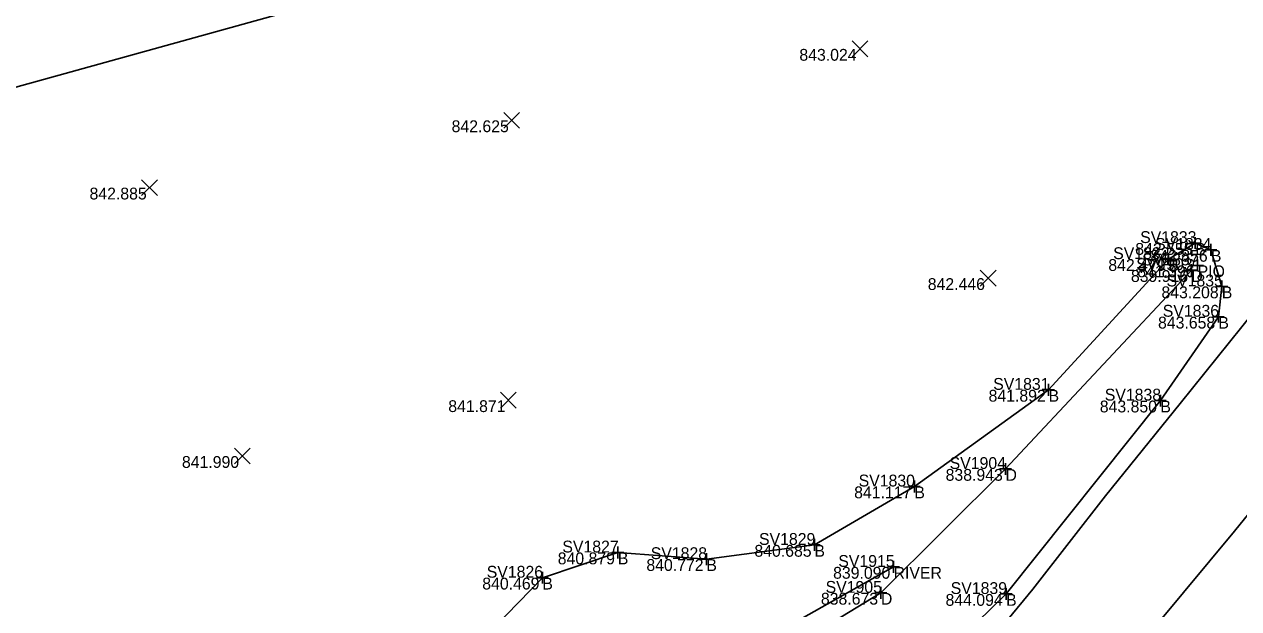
# Model space of a CAD drawing. Extents: x 2125299 to 2129212, y 713100 to 714300.
# Drawn here: x 2127803.8 to 2127906.4, y 713620.7 to 713670.1 of the extents above; entities that cross this region are included whole.
import ezdxf

# ---------------------------------------------------------------- set-up
doc = ezdxf.new("R2010")
doc.units = 0
for name, color, linetype in [('DR_X_Ditch', 7, 'Continuous'), ('HY_X_Water_Edge', 7, 'Continuous'), ('PM_X_CL_Double_Solid', 7, 'Continuous'), ('PV_X_EOP', 7, 'Continuous'), ('RD_X_Fence', 7, 'Continuous'), ('RW_P_Esmt_TMP', 7, 'Continuous'), ('RW_X_CL_100_Cardinal_Points', 7, 'Continuous'), ('RW_X_Esmt_CH', 7, 'Continuous'), ('RW_X_Fee_WL', 7, 'Continuous'), ('SV_X_Break_Lines', 7, 'Continuous'), ('SV_X_Mon_Cells_Found', 7, 'Continuous'), ('SV_X_Text_Elevation', 7, 'Continuous')]:
    doc.layers.add(name, color=color, linetype=linetype)

msp = doc.modelspace()

# ---------------------------------------------------------------- linework, layer by layer
at = {"layer": 'DR_X_Ditch'}
msp.add_lwpolyline([(2127902.43, 713649.34), (2127886.72, 713632.53), (2127876.19, 713622.06), (2127870.21, 713618.42), (2127864.69, 713612.09), (2127851.92, 713612.64), (2127839.65, 713605.25), (2127835.51, 713593.15)], dxfattribs=at)
at = {"layer": 'HY_X_Water_Edge'}
msp.add_lwpolyline([(2127760.76, 713650.39), (2127768.15, 713637.25), (2127774.73, 713633.04), (2127778.54, 713623.49), (2127790.38, 713611.58), (2127799.45, 713605.77), (2127811.76, 713595.2), (2127821.63, 713592.89), (2127831.56, 713597.95), (2127834.89, 713597.21), (2127837.24, 713606.78), (2127846.53, 713615.95), (2127858.46, 713615.16), (2127864.19, 713615.01), (2127868.76, 713619.47), (2127877.26, 713624.25)], dxfattribs=at)
at = {"layer": 'PM_X_CL_Double_Solid'}
msp.add_lwpolyline([(2127847.25, 713559.16), (2127853.89, 713566.63), (2127860.53, 713574.11), (2127867.15, 713581.61), (2127873.74, 713589.13), (2127880.29, 713596.69), (2127886.77, 713604.3), (2127893.23, 713611.93), (2127899.68, 713619.58), (2127906.08, 713627.26), (2127912.37, 713635.04)], dxfattribs=at)
at = {"layer": 'PV_X_EOP'}
msp.add_lwpolyline([(2127836.75, 713561.85), (2127843.31, 713569.4), (2127849.87, 713576.94), (2127856.63, 713584.32), (2127863.34, 713591.74), (2127869.93, 713599.25), (2127876.3, 713606.96), (2127882.68, 713614.67), (2127889.03, 713622.38), (2127895.18, 713630.27), (2127901.47, 713638.05), (2127907.73, 713645.84)], dxfattribs=at)
at = {"layer": 'RD_X_Fence'}
msp.add_lwpolyline([(2127758.11, 713652.62), (2127783.85, 713659.47), (2127880.44, 713686.28), (2127925.78, 713698.52)], dxfattribs=at)
at = {"layer": 'RW_X_CL_100_Cardinal_Points'}
for p, q in [((2127902.46, 713649.74), (2127903.46, 713649.74)), ((2127902.96, 713650.24), (2127902.96, 713649.24)), ((2127902.96, 713649.74), (2127902.96, 713649.74))]:
    msp.add_line(p, q, dxfattribs=at)
at = {"layer": 'SV_X_Break_Lines'}
msp.add_lwpolyline([(2127802.01, 713616.51), (2127817.35, 713616.43), (2127841.48, 713617.04), (2127847.58, 713623.34), (2127853.96, 713625.47), (2127861.44, 713624.91), (2127870.57, 713626.11), (2127879.02, 713631.05), (2127890.36, 713639.22), (2127900.49, 713650.27), (2127902.76, 713651.63), (2127904.08, 713651.05), (2127905, 713647.96), (2127904.71, 713645.4), (2127899.81, 713638.31), (2127886.77, 713621.96), (2127875.58, 713611.04), (2127866.65, 713606.54), (2127858.53, 713606.15), (2127852.92, 713601.22), (2127853.26, 713594.46), (2127852.23, 713583.37), (2127850.69, 713586.06)], dxfattribs=at)
at = {"layer": 'SV_X_Mon_Cells_Found'}
for p, q in [((2127902.26, 713651.63), (2127903.26, 713651.63)), ((2127902.76, 713652.13), (2127902.76, 713651.13)), ((2127902.76, 713651.63), (2127902.76, 713651.63)), ((2127904.08, 713651.55), (2127904.08, 713650.55)), ((2127900.49, 713650.77), (2127900.49, 713649.77)), ((2127903.58, 713651.05), (2127904.58, 713651.05)), ((2127904.08, 713651.05), (2127904.08, 713651.05)), ((2127899.99, 713650.27), (2127900.99, 713650.27)), ((2127900.49, 713650.27), (2127900.49, 713650.27)), ((2127902.43, 713649.84), (2127902.43, 713648.84)), ((2127901.93, 713649.34), (2127902.93, 713649.34)), ((2127902.43, 713649.34), (2127902.43, 713649.34)), ((2127905, 713648.46), (2127905, 713647.46)), ((2127904.5, 713647.96), (2127905.5, 713647.96)), ((2127905, 713647.96), (2127905, 713647.96)), ((2127904.21, 713645.4), (2127905.21, 713645.4)), ((2127904.71, 713645.9), (2127904.71, 713644.9)), ((2127904.71, 713645.4), (2127904.71, 713645.4)), ((2127889.86, 713639.22), (2127890.86, 713639.22)), ((2127890.36, 713639.72), (2127890.36, 713638.72)), ((2127890.36, 713639.22), (2127890.36, 713639.22)), ((2127899.31, 713638.31), (2127900.31, 713638.31)), ((2127899.81, 713638.81), (2127899.81, 713637.81)), ((2127899.81, 713638.31), (2127899.81, 713638.31)), ((2127886.22, 713632.53), (2127887.22, 713632.53)), ((2127886.72, 713633.03), (2127886.72, 713632.03)), ((2127886.72, 713632.53), (2127886.72, 713632.53)), ((2127878.52, 713631.05), (2127879.52, 713631.05)), ((2127879.02, 713631.55), (2127879.02, 713630.55)), ((2127879.02, 713631.05), (2127879.02, 713631.05)), ((2127853.96, 713625.97), (2127853.96, 713624.97)), ((2127870.07, 713626.11), (2127871.07, 713626.11)), ((2127870.57, 713626.61), (2127870.57, 713625.61)), ((2127870.57, 713626.11), (2127870.57, 713626.11)), ((2127853.46, 713625.47), (2127854.46, 713625.47)), ((2127853.96, 713625.47), (2127853.96, 713625.47)), ((2127860.94, 713624.91), (2127861.94, 713624.91)), ((2127861.44, 713625.41), (2127861.44, 713624.41)), ((2127861.44, 713624.91), (2127861.44, 713624.91)), ((2127847.58, 713623.84), (2127847.58, 713622.84)), ((2127876.76, 713624.25), (2127877.76, 713624.25)), ((2127877.26, 713624.75), (2127877.26, 713623.75)), ((2127877.26, 713624.25), (2127877.26, 713624.25)), ((2127847.08, 713623.34), (2127848.08, 713623.34)), ((2127847.58, 713623.34), (2127847.58, 713623.34)), ((2127875.69, 713622.06), (2127876.69, 713622.06)), ((2127876.19, 713622.56), (2127876.19, 713621.56)), ((2127876.19, 713622.06), (2127876.19, 713622.06)), ((2127886.27, 713621.96), (2127887.27, 713621.96)), ((2127886.77, 713622.46), (2127886.77, 713621.46)), ((2127886.77, 713621.96), (2127886.77, 713621.96))]:
    msp.add_line(p, q, dxfattribs=at)
at = {"layer": 'SV_X_Text_Elevation'}
for p, q in [((2127873.76, 713667.38), (2127875.09, 713668.71)), ((2127873.76, 713668.71), (2127875.09, 713667.38)), ((2127844.31, 713661.33), (2127845.65, 713662.67)), ((2127844.31, 713662.67), (2127845.65, 713661.33)), ((2127813.71, 713655.64), (2127815.05, 713656.98)), ((2127813.71, 713656.98), (2127815.05, 713655.64)), ((2127884.58, 713647.99), (2127885.92, 713649.33)), ((2127884.58, 713649.33), (2127885.92, 713647.99)), ((2127844.04, 713637.67), (2127845.37, 713639.01)), ((2127844.04, 713639.01), (2127845.37, 713637.67)), ((2127821.57, 713632.96), (2127822.9, 713634.29)), ((2127821.57, 713634.29), (2127822.9, 713632.96))]:
    msp.add_line(p, q, dxfattribs=at)

# ---------------------------------------------------------------- texts
at = {"layer": 'RW_P_Esmt_TMP'}
for s, p in [('B', (2127902.76, 713650.63)), ('B', (2127904.08, 713650.05)), ('B', (2127900.49, 713649.27)), ('PIO', (2127902.96, 713648.74)), ('D', (2127902.43, 713648.34)), ('B', (2127905, 713646.96)), ('B', (2127904.71, 713644.4)), ('B', (2127890.36, 713638.22)), ('B', (2127899.81, 713637.31)), ('D', (2127886.72, 713631.53)), ('B', (2127879.02, 713630.05)), ('B', (2127870.57, 713625.11)), ('B', (2127853.96, 713624.47)), ('B', (2127861.44, 713623.91)), ('RIVER', (2127877.26, 713623.25)), ('B', (2127847.58, 713622.34)), ('D', (2127876.19, 713621.06)), ('B', (2127886.77, 713620.96))]:
    msp.add_text(s, height=1, dxfattribs=at).set_placement(p)
at = {"layer": 'RW_X_Esmt_CH'}
for s, p in [('SV1833', (2127898.1, 713651.63)), ('SV1834', (2127899.36, 713651.05)), ('SV1832', (2127895.82, 713650.27)), ('SV1837', (2127898.27, 713649.74)), ('SV1903', (2127897.77, 713649.34)), ('SV1835', (2127900.33, 713647.96)), ('SV1836', (2127900.01, 713645.4)), ('SV1831', (2127885.68, 713639.22)), ('SV1838', (2127895.11, 713638.31)), ('SV1904', (2127882, 713632.53)), ('SV1830', (2127874.31, 713631.05)), ('SV1829', (2127865.89, 713626.11)), ('SV1827', (2127849.27, 713625.47)), ('SV1828', (2127856.74, 713624.91)), ('SV1915', (2127872.59, 713624.25)), ('SV1826', (2127842.88, 713623.34)), ('SV1905', (2127871.52, 713622.06)), ('SV1839', (2127882.09, 713621.96))]:
    msp.add_text(s, height=1, dxfattribs=at).set_placement(p)
at = {"layer": 'RW_X_Fee_WL'}
for s, p in [('843.024', (2127869.3, 713667.04)), ('842.625', (2127839.91, 713661)), ('842.885', (2127809.31, 713655.31)), ('842.555', (2127897.69, 713650.63)), ('842.856', (2127898.97, 713650.05)), ('842.479', (2127895.41, 713649.27)), ('841.396', (2127897.86, 713648.74)), ('842.446', (2127880.15, 713647.66)), ('839.916', (2127897.32, 713648.34)), ('843.208', (2127899.9, 713646.96)), ('843.658', (2127899.61, 713644.4)), ('841.892', (2127885.29, 713638.22)), ('841.871', (2127839.63, 713637.34)), ('843.850', (2127894.69, 713637.31)), ('841.990', (2127817.12, 713632.62)), ('838.943', (2127881.66, 713631.53)), ('841.117', (2127873.93, 713630.05)), ('840.685', (2127865.5, 713625.11)), ('840.879', (2127848.88, 713624.47)), ('840.772', (2127856.37, 713623.91)), ('839.090', (2127872.15, 713623.25)), ('840.469', (2127842.5, 713622.34)), ('838.673', (2127871.12, 713621.06)), ('844.094', (2127881.65, 713620.96))]:
    msp.add_text(s, height=1, dxfattribs=at).set_placement(p)

doc.saveas('drawing.dxf')
